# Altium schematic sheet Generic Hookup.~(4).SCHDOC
size Tabloid; Organization: Monterey Bay Aquarium Research Institute; Address1: 7700 Sandholdt Rd; Address2: Moss Landing, CA 95039-9644; CompanyName: MBARI; PageSetup: Record=PageOptions|CenterHorizontal=True|CenterVertical=True|PrintScale=0.95|XCorrection=1.00|YCorrection=1.00|PrintKind=0|BorderSize=5000000|LeftOffset=0|BottomOffset=0|Orientation=2|PaperLength=1000|PaperWidth=1000|Scale=100|PaperSource=7|PrintQuality=-4|MediaType=1|DitherType=10|PaperKind=11x17|PrintScaleMode=1
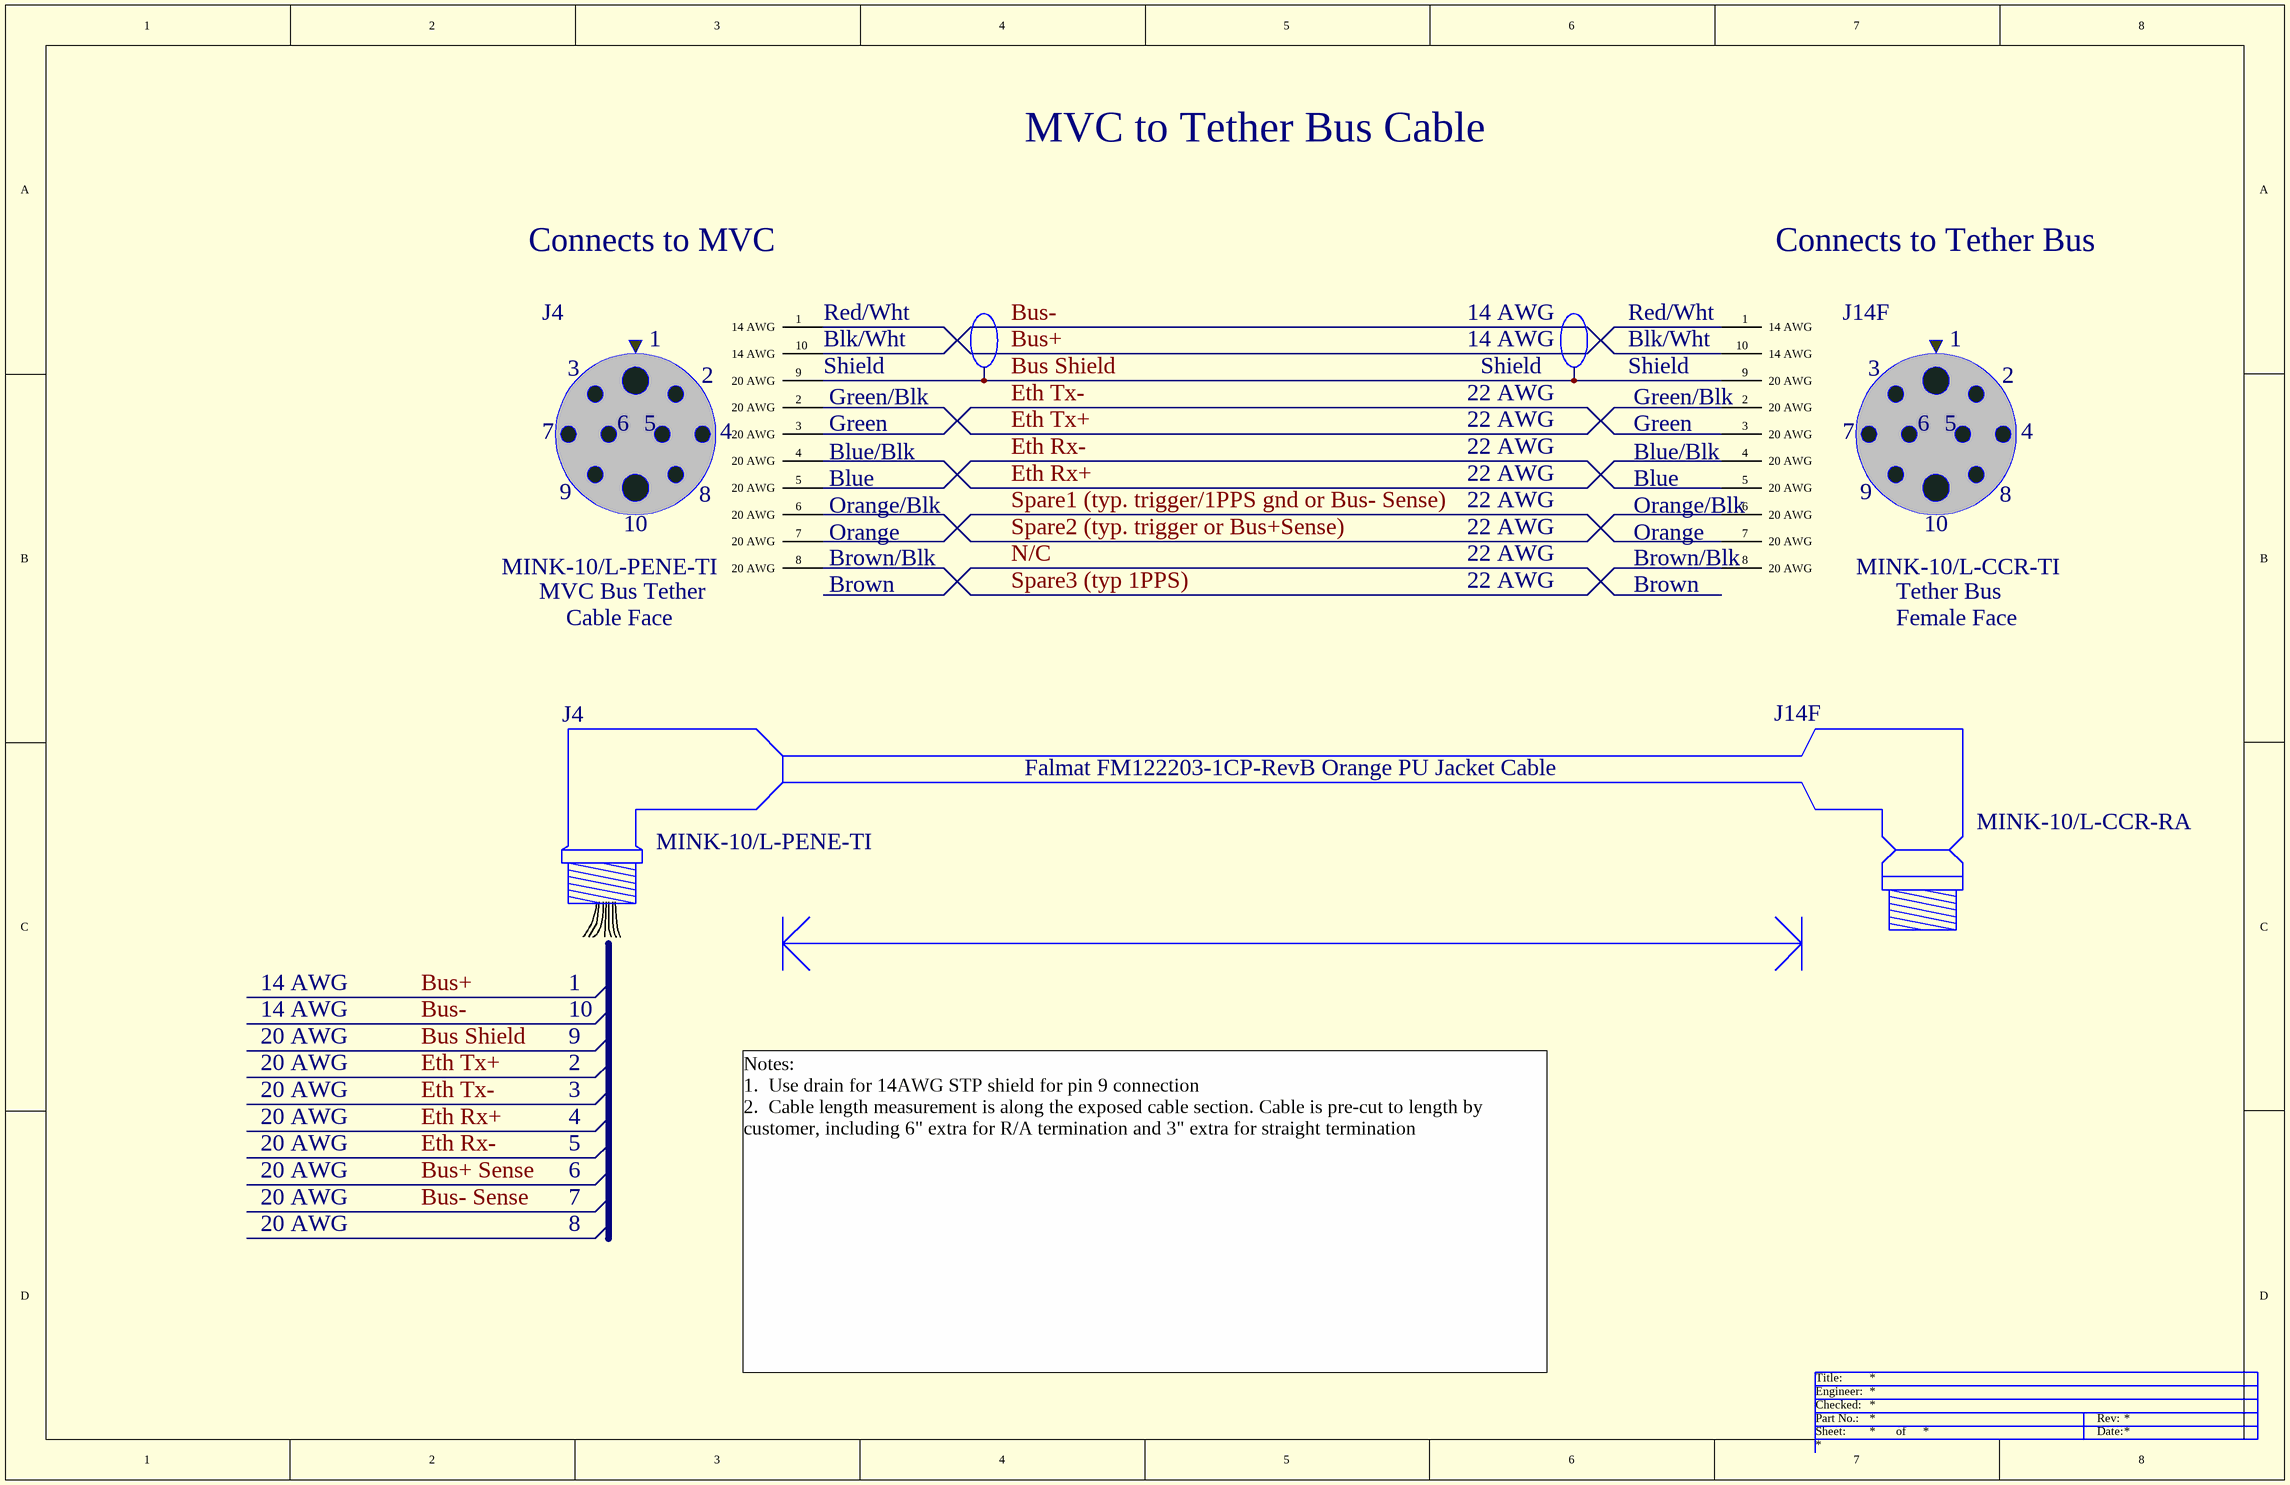
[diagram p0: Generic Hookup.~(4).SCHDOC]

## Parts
(Parts that share a designator on the sheet are numbered #1, #2 ... from top to bottom, then left to right.)
J4#1  MINK-10/L-PENE-TI  DescSheet: MVC Bus Tether  View: Cable Face
J4#2  MINK-10/L-PENE-TI
J14F#1  MINK-10/L-CCR-TI  DescSheet: Tether Bus  View: Female Face
J14F#2  MINK-10/L-CCR-RA

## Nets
Bus Shield: J4#1.9(20_AWG) J14F#1.9(20_AWG)
Bus+: J4#1.1(14_AWG) J14F#1.1(14_AWG)
Bus-: J4#1.10(14_AWG) J14F#1.10(14_AWG)
Eth Rx+: J4#1.4(20_AWG) J14F#1.4(20_AWG)
Eth Rx-: J4#1.5(20_AWG) J14F#1.5(20_AWG)
Eth Tx+: J4#1.2(20_AWG) J14F#1.2(20_AWG)
Eth Tx-: J4#1.3(20_AWG) J14F#1.3(20_AWG)
Spare1 (typ. trigger/1PPS gnd or Bus- Sense): J4#1.7(20_AWG) J14F#1.7(20_AWG)
Spare2 (typ. trigger or Bus+Sense): J4#1.6(20_AWG) J14F#1.6(20_AWG)
Spare3 (typ 1PPS): J4#1.8(20_AWG) J14F#1.8(20_AWG)

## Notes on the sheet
- MVC to Tether Bus Cable
- Connects to MVC
- Connects to Tether Bus
- (near J4#1) Red/Wht
- (near J4#1) Blk/Wht
- 14 AWG
- (near J14F#1) Red/Wht
- (near J14F#1) Blk/Wht
- (near J4#1) Shield
- (near J4#1) Green
- (near J4#1) Green/Blk
- 22 AWG
- Shield
- Green
- (near J14F#1) Green/Blk
- (near J4#1) Blue/Blk
- (near J4#1) Blue
- (near J14F#1) Blue/Blk
- Blue
- (near J4#1) Brown/Blk
- (near J4#1) Orange
- (near J4#1) Orange/Blk
- (near J14F#1) Brown/Blk
- Orange
- (near J14F#1) Orange/Blk
- (near J4#1) Brown
- Brown
- Falmat FM122203-1CP-RevB Orange PU Jacket Cable
- 1
- 10
- 20 AWG
- 2
- 3
- 9
- 4
- 5
- 6
- 7
- 8
- Notes:
  1.  Use drain for 14AWG STP shield for pin 9 connection
  2.  Cable length measurement is along the exposed cable section. Cable is pre-cut to length by customer, including 6" extra for R/A termination and 3" extra for straight termination

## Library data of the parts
J4#1 J14F#1 = SEACON-MINK-10-BCR-PINS: Manufacturer: Seacon
J4#2 = CONN-MIN-PENE-LARGE: Seacon MIN Penetrator
J14F#2 = CONN-MIN-CCR-RA-LARGE: Seacon MIN Connector CCR Right Angle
